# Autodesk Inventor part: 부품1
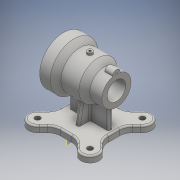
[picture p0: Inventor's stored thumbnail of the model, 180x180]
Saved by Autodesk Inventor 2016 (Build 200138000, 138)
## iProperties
Created: 2017-03
Part Number: 부품1
Material: 일반
Document SubType Name: Modeling
Designer: USER
Density: 1 g/cm^3
Appearance: 기본값
Author: USER
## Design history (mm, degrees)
sketch "스케치1"
  geometry: L1 (0, 0)-(70, 0); L2 (0, 0)-(70, 0); L3 (45, 21.136)-(45, -21.136); L4 (21.136, -45)-(-21.136, -45); L5 (-36.106, -59.97)-(-21.136, -45); L6 (-36.106, -59.97)-(-14.936, -59.97); L7 (-59.97, -36.106)-(-45, -21.136); L8 (-59.97, -36.106)-(-38.799, -36.106); L9 (-59.97, 36.106)-(-45, 21.136); L10 (-59.97, 36.106)-(-39.025, 36.106); L11 (-36.106, 59.97)-(-21.136, 45); L12 (-36.106, 59.97)-(-14.936, 59.97); L13 (36.106, 59.97)-(21.136, 45); L14 (36.106, 59.97)-(57.276, 59.97); L15 (59.97, 36.106)-(45, 21.136); L16 (59.97, 36.106)-(81.14, 36.106); L17 (36.106, -59.97)-(21.136, -45); L18 (36.106, -59.97)-(57.276, -59.97); L19 (59.97, -36.106)-(45, -21.136); L20 (59.97, -36.106)-(81.14, -36.106); L21 (45, -45)-(37.477, -37.477); L22 (0, 0)-(-45, 45); L23 (45, 45)-(37.477, 37.477); L24 (-45, -21.136)-(-45, 21.136); L25 (-21.136, 45)-(21.136, 45); A1 r 17 centre (49.497, 49.497) between (59.97, 36.106) and (36.106, 59.97); A2 r 17 centre (-49.497, -49.497) between (-59.97, -36.106) and (-36.106, -59.97); A3 r 17 centre (49.497, -49.497) between (36.106, -59.97) and (59.97, -36.106); A4 r 17 centre (-49.497, 49.497) between (-36.106, 59.97) and (-59.97, 36.106)
  constraints: 50 end point, 10 horizontal, 8 point on circle, 7 equal length, 4 centre point, 2 parallel, 1 perpendicular, 1 vertical
  dimensions: "d120" = 34 diameter of A1; "d123" = 45 deg angle of L6 L5; "d124" = 45 deg angle of L8 L7; "d125" = 45 deg angle of L9 L10; "d126" = 45 deg angle of L11 L12; "d127" = 135 deg angle of L13 L14; "d128" = 135 deg angle of L15 L16; "d129" = 135 deg angle of L18 L17; "d130" = 135 deg angle of L20 L19
extrude "돌출1" new body sketch "스케치1" distance "d15" = 12; taper "d16" = 0 deg
sketch "스케치2"
  geometry: L1 (-35, 4)-(39, 4); L2 (39, 4)-(39, -4); L3 (39, -4)-(-35, -4); L4 (-35, -4)-(-35, 4); 1 further point
  constraints: 8 end point, 2 parallel, 1 horizontal, 1 perpendicular
  dimensions: "d18" = 4 distance from line of point (0, 0) L1; "d88" = 74 distance of L1.start L1.end; "d89" = 35 distance from line of point (0, 0) L4; "d90" = 4 distance from line of L3 point (0, 0)
node "작업 평면4"
revolve "회전1" stored, may be unused: angle "d29" = 90 deg
node "작업 평면5"
revolve "회전2" stored, may be unused: angle "d33" = 90 deg
sketch "스케치6"
  geometry: 2 further points
hole "구멍1" sketch "스케치6" at (40, 0) diameter "d41" = 3.242; stored, may be unused: countersink angle "d45" = 90 deg, drill point angle "d47" = 118 deg; dims "d42" = 9, "d43" = 4, "d44" = 2, "d46" = 11
node "작업 평면6"
sketch "스케치7"
  geometry: L1 (60.001, 109.5)-(83.001, 109.5) reference; L2 (83.001, 54.5)-(83.001, 109.5) reference; L3 (83.001, 109.5)-(83.001, 116.5); L4 (83.001, 116.5)-(68.001, 116.5); L5 (68.001, 116.5)-(68.001, 109.5); L6 (68.001, 109.5)-(83.001, 109.5); 1 further point
  constraints: 8 end point, 3 perpendicular, 2 point on line
  dimensions: "d51" = 7 distance of L3.start L3.end; "d52" = 15 distance of L3.end L4.end; "d53" = 0 distance between parallel lines of L1 L6
revolve "회전4" sketch "스케치7" stored, may be unused: angle "d54" = 90 deg
sketch "스케치8"
  geometry: A1 r 27.5 centre (27.5, 0) between (0.891, -6.943) and (0.891, 6.943) reference; A2 r 7 centre (0, 0) between (0.891, 6.943) and (0.891, -6.943) reference; 2 further points
hole "구멍2" sketch "스케치8" diameter "d60" = 3.242; stored, may be unused: countersink angle "d64" = 90 deg, drill point angle "d66" = 118 deg; dims "d61" = 9, "d62" = 4, "d63" = 2, "d65" = 11
extrude "돌출2" join sketch "스케치2" distance "d91" = 82; taper "d92" = 0 deg
node "작업 평면8"
sketch "스케치10"
  geometry: L1 (0, 0)-(0, 66.003) reference; L2 (0, 0)-(12, 0) reference; L3 (12, 66.003)-(12, 0) reference; L4 (0, 66.003)-(12, 66.003) reference; L5 (0, -10.132)-(0, 0) reference; L6 (0, -10.132)-(12, -10.132) reference; L7 (12, 0)-(12, -10.132) reference; L8 (0, 0)-(12, 0) reference; L9 (0, 66.003)-(0, 76.135) reference; L10 (0, 66.003)-(12, 66.003) reference; L11 (12, 76.135)-(12, 66.003) reference; L12 (0, 76.135)-(12, 76.135) reference; L13 (12, 66.003)-(12, 0) reference; L14 (12, 33.001)-(12, 8.001); L15 (12, 8.001)-(82, 20.344); L16 (12, 33.001)-(12, 58.001); L17 (12, 58.001)-(82, 45.658); L18 (82, 45.658)-(82, 20.344); 1 further point
  constraints: 10 end point, 2 point on line, 1 midpoint, 1 parallel
  dimensions: "d93" = 25 distance of L14.start L14.end; "d94" = 80 deg angle of L15 L14; "d95" = 25 distance of L14.start L16.end; "d96" = 80 deg angle of L16 L17; "d97" = 82 distance between parallel lines of L1 L18
extrude "돌출3" join sketch "스케치10" stored distance "d98" = 8; taper "d99" = 0 deg
node "작업 평면3"
sketch "스케치11"
  geometry: 1 further point
node "작업 평면10"
sketch "스케치12"
  geometry: L1 (72.001, 54.792)-(60.001, 54.792) reference; L2 (60.001, 54.792)-(60.001, 54.792) reference; L3 (60.001, 54.792)-(72.001, 54.792) reference; L4 (72.001, 54.792)-(72.001, 54.792) reference; L5 (83.001, 108.609)-(83.001, 108.609) reference; L6 (48.001, 46.223)-(48.001, 46.223) reference; L7 (60.001, 54.792)-(60.001, 54.792) reference; L8 (14.001, 118)-(48.001, 118) reference; L9 (-16.999, 127)-(3.001, 127) reference; L10 (-16.999, 37)-(-16.999, 127) reference; L11 (66.003, 0)-(0, 0) reference; L12 (-16.999, 82)-(83.001, 82); L13 (83.001, 82)-(83.001, 99.5); L14 (83.001, 99.5)-(53.001, 99.5); L15 (53.001, 99.5)-(53.001, 108); L16 (53.001, 108)-(6.001, 108); L17 (6.001, 108)-(6.001, 117); L18 (6.001, 117)-(-16.999, 117); L19 (68.001, 108.609)-(83.001, 108.609) reference; L20 (83.001, 108.609)-(68.001, 108.609) reference; L21 (68.001, 108.609)-(68.001, 108.609) reference; 5 further points; 1 other entity
  constraints: 14 end point, 4 perpendicular, 1 horizontal, 1 midpoint, 1 point on line, 5 other
  dimensions: "d100" = 23 distance of L17.end L18.end; "d101" = 47 distance of L15.end L16.end; "d102" = 70 diameter of L18 L12; "d103" = 52 diameter of L16 L12; "d104" = 35 diameter of L14 L12
revolve "회전5" sketch "스케치12" stored, may be unused: angle "d105" = 90 deg
sketch "스케치13"
  geometry: L1 (0, 0)-(70, 0); L2 (0, 0)-(70, 0); L3 (0, 0)-(70, 0); L4 (0, 0)-(70, 0); C1 r 5 at (49.497, 49.497); C2 r 5 at (49.497, -49.497); C3 r 5 at (-49.497, -49.497); C4 r 5 at (-49.497, 49.497); 1 further point
  constraints: 8 end point, 4 centre point, 4 horizontal, 1 coincident
  dimensions: "d136" = 10 diameter of C1; "d137" = 10 diameter of C2; "d138" = 10 diameter of C3; "d139" = 10 diameter of C4
extrude "돌출4" cut sketch "스케치13" stored distance "d140" = 10; taper "d141" = 0 deg
fillet "모깎기8" dims "d142" = 3
fillet "모깎기9" dims "d143" = 25
fillet "모깎기10" dims "d144" = 3
fillet "모깎기11" dims "d145" = 3
sketch "스케치14"
  geometry: 2 further points
  constraints: 1 coincident
hole "구멍4" sketch "스케치14" at (0, 0) diameter "d146" = 4.134; stored, may be unused: countersink angle "d150" = 90 deg, drill point angle "d152" = 118 deg; dims "d147" = 10, "d148" = 4, "d149" = 2, "d151" = 20
node "솔리드1"
sketch "스케치3"
  geometry: L1 (-16.999, 82)-(83.001, 82); L2 (-16.999, 82)-(-16.999, 127); L3 (-16.999, 127)-(3.001, 127); L4 (3.001, 127)-(14.001, 118); L5 (14.001, 118)-(48.001, 118); L6 (48.001, 118)-(60.001, 109.5); L7 (60.001, 109.5)-(83.001, 109.5); L8 (83.001, 109.5)-(83.001, 82); L9 (66.003, 0)-(0, 0) reference; L10 (66.003, 12)-(0, 12) reference; 1 further point
  constraints: 16 end point, 2 horizontal, 2 perpendicular, 1 parallel, 1 vertical
  dimensions: "d19" = 90 diameter of L3 L1; "d20" = 72 diameter of L5 L1; "d21" = 55 diameter of L7 L1; "d22" = 82 distance between parallel lines of L9 L1; "d23" = 20 distance of L2.end L3.end; "d24" = 31 horizontal distance of L4.end L2.end; "d25" = 65 horizontal distance of L2.end L5.end; "d26" = 100 distance between parallel lines of L8 L2; "d27" = 23 distance of L6.end L7.end
sketch "스케치4"
  geometry: L1 (33.001, 0)-(33.001, 122); L2 (83.001, 54.5)-(83.001, 109.5) reference; L3 (83.001, 82)-(23.823, 82); L4 (14.001, 118)-(48.001, 118) reference; L5 (33.001, 122)-(28.001, 122); L6 (28.001, 122)-(28.001, 112); L7 (28.001, 112)-(33.001, 112)
  constraints: 10 end point, 2 horizontal, 2 perpendicular, 1 midpoint, 1 point on line, 1 vertical
  dimensions: "d30" = 40 distance between parallel lines of L3 L5; "d31" = 5 distance of L1.end L5.end; "d32" = 10 distance between parallel lines of L5 L7
node "투영된 루프1"
node "투영된 루프2"
node "투영된 루프3"
node "투영된 루프4"
node "투영된 루프5"
node "투영된 루프6"
other parameters: "d3" = 45, "d4" = 45, "d6" = 17, "d7" = 17, "d8" = 17, "d9" = 17, "d117" = 34, "d118" = 34, "d119" = 34
